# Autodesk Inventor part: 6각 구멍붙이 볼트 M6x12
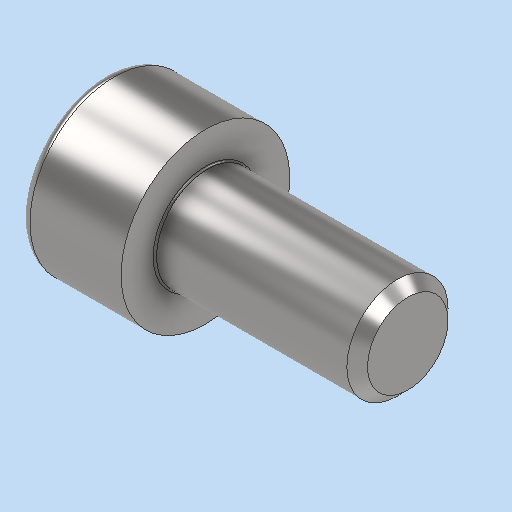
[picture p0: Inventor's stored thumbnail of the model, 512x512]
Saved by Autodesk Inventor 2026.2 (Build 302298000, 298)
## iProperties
Created: 2026-01
Part Number: 6각 구멍붙이 볼트 M6x12
Material: 강철, 연강
Description: 6각머리 태핑 나사
Document SubType Name: Modeling
Designer: PC2-07
Density: 7.85 g/cm^3
Appearance: 기본값
Author: jhkim
Sending System: Autodesk Inventor 2026
Preprocessor: ST-DEVELOPER v20.1
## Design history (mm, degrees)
feature "Solid1"
node "솔리드1"
